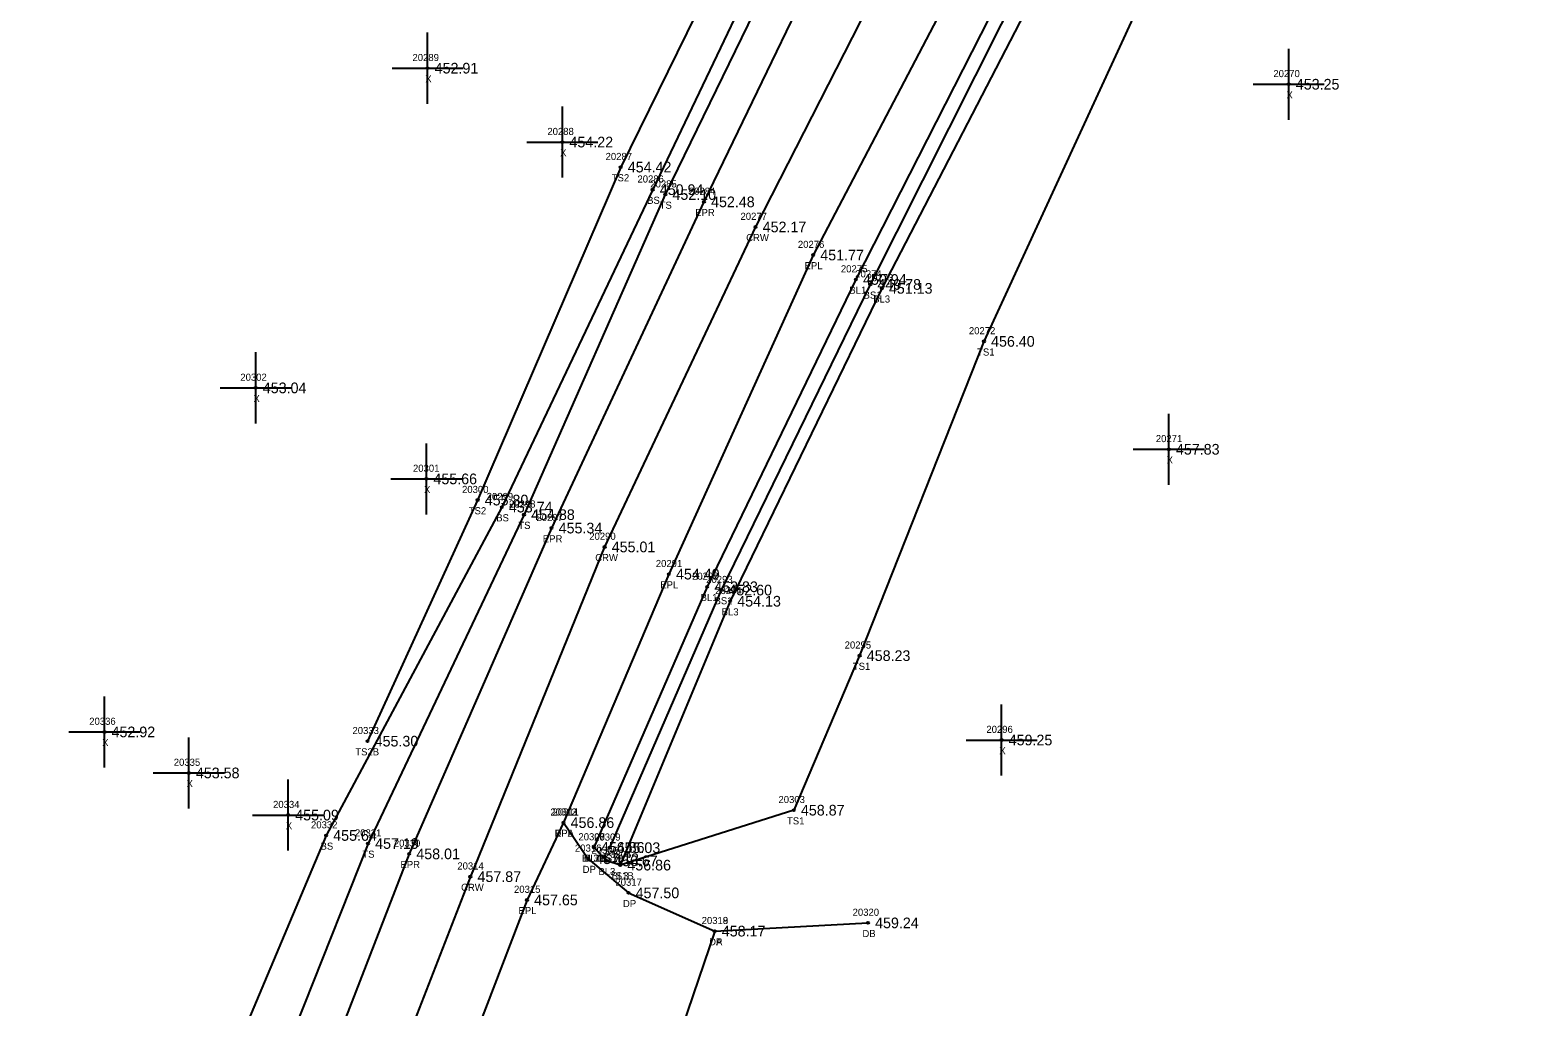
# Model space of a CAD drawing. Extents: x 1763022 to 1764007, y 824123 to 825394.
# Drawn here: x 1763289.5 to 1763501.5, y 824553.5 to 824690.9 of the extents above; entities that cross this region are included whole.
import ezdxf

# ---------------------------------------------------------------- set-up
doc = ezdxf.new("R2010")
doc.units = 0
for name, color, linetype in [('RD_DTM_BkLn1', 7, 'Continuous'), ('RD_DTM_BkLn2', 7, 'Continuous'), ('RD_DTM_BkLn_txCode', 7, 'Continuous'), ('RD_EX_Driveway', 7, 'Continuous'), ('RD_EX_Driveway_txCode', 7, 'Continuous'), ('RD_EX_Misc', 7, 'Continuous'), ('RD_EX_Misc_txCode', 7, 'Continuous'), ('RD_EX_Road', 7, 'Continuous'), ('RD_EX_Road_txCode', 7, 'Continuous'), ('RD_EX_TX_Driveway_ELEV', 7, 'Continuous'), ('RD_EX_TX_Misc_ELEV', 7, 'Continuous'), ('RD_EX_TX_Road_ELEV', 7, 'Continuous'), ('RD_HC_Survey_ELEV', 7, 'Continuous'), ('RD_HC_Survey_txCode', 7, 'Continuous'), ('RD_SMD_Locator', 7, 'Continuous')]:
    doc.layers.add(name, color=color, linetype=linetype)

msp = doc.modelspace()

# ---------------------------------------------------------------- linework, layer by layer
at = {"layer": 'RD_DTM_BkLn1'}
for points in [[(1763465.6, 824795.18), (1763438.99, 824751.97), (1763414.16, 824707.73), (1763391.5, 824663.21), (1763370.27, 824618.19), (1763351.39, 824571.8), (1763333.36, 824525.39), (1763297, 824431.97), (1763261.49, 824337.79), (1763225.86, 824243.32), (1763189.96, 824148.95)], [(1763449.11, 824737.2), (1763428.21, 824700.24), (1763405.61, 824655.82), (1763384.69, 824612.58), (1763368.75, 824575.91)], [(1763452.61, 824734.75), (1763432, 824698.5), (1763409.25, 824654.57), (1763387.93, 824610.55), (1763372.47, 824573.42), (1763370.6, 824574.02), (1763368.75, 824575.91)]]:
    msp.add_lwpolyline(points, dxfattribs=at)
at = {"layer": 'RD_DTM_BkLn2'}
for points in [[(1763437.34, 824834), (1763430.66, 824820.06), (1763415.77, 824811.96), (1763415.35, 824798.51), (1763416.46, 824790.14), (1763418.19, 824781.43), (1763421.71, 824775.16), (1763417.19, 824763.87), (1763415.91, 824751.32), (1763399.06, 824714.58), (1763377.03, 824668.46), (1763355.81, 824623.79), (1763331.1, 824577.59), (1763312.25, 824532.84), (1763306.13, 824522.15), (1763306.75, 824510.59), (1763289.07, 824468.95), (1763279.57, 824438.1), (1763246.06, 824343.25), (1763209.87, 824247.25), (1763175.28, 824154.06)], [(1763453.01, 824802.49), (1763449.47, 824806.22), (1763441.02, 824809.92), (1763431.56, 824802.85), (1763425.71, 824792.63), (1763430.16, 824781.29), (1763430.95, 824776.81), (1763424.71, 824760.36), (1763418.93, 824749.28), (1763401.15, 824713.73), (1763378.81, 824667.77), (1763358.94, 824622.73), (1763337, 824576.46), (1763318.92, 824530.87), (1763314.75, 824518.63), (1763292.84, 824467.34), (1763282.85, 824437.24), (1763248.29, 824342.54), (1763211.77, 824246.85), (1763177.66, 824153.22)], [(1763510.31, 824776.41), (1763487.73, 824739.69), (1763467.72, 824746.4), (1763457.88, 824742.49), (1763448.32, 824732.5), (1763429.76, 824699.16), (1763407.64, 824655.12), (1763386.68, 824612.12), (1763370.96, 824575.87)], [(1763412.55, 824767.8), (1763413.66, 824764.06), (1763414.47, 824751.79), (1763395.05, 824717.48), (1763372.53, 824671.63), (1763352.41, 824624.78), (1763336.93, 824590.86)], [(1763459.29, 824736.58), (1763444.88, 824693.27), (1763423.62, 824647.11), (1763406.14, 824602.89), (1763396.88, 824581.15), (1763372.47, 824573.42)]]:
    msp.add_lwpolyline(points, dxfattribs=at)
at = {"layer": 'RD_EX_Driveway'}
msp.add_line((1763385.75, 824564.13), (1763407.31, 824565.29), dxfattribs=at)
msp.add_lwpolyline([(1763364.49, 824579.4), (1763367.96, 824574.32), (1763373.63, 824569.51), (1763385.75, 824564.13), (1763378.09, 824541.5), (1763366.26, 824546.2), (1763360.49, 824545.69), (1763347.68, 824537.95)], dxfattribs=at)
at = {"layer": 'RD_EX_Misc'}
for p, q in [((1763345.37, 824680.55), (1763345.37, 824690.55)), ((1763466.48, 824678.29), (1763466.48, 824688.29)), ((1763340.37, 824685.55), (1763350.37, 824685.55)), ((1763461.48, 824683.29), (1763471.48, 824683.29)), ((1763364.33, 824670.15), (1763364.33, 824680.15)), ((1763359.33, 824675.15), (1763369.33, 824675.15)), ((1763321.2, 824635.57), (1763321.2, 824645.57)), ((1763316.2, 824640.57), (1763326.2, 824640.57)), ((1763449.62, 824626.93), (1763449.62, 824636.93)), ((1763345.2, 824622.76), (1763345.2, 824632.76)), ((1763444.62, 824631.93), (1763454.62, 824631.93)), ((1763340.2, 824627.76), (1763350.2, 824627.76)), ((1763299.93, 824587.16), (1763299.93, 824597.16)), ((1763426.1, 824586.02), (1763426.1, 824596.02)), ((1763294.93, 824592.16), (1763304.93, 824592.16)), ((1763311.79, 824581.39), (1763311.79, 824591.39)), ((1763421.1, 824591.02), (1763431.1, 824591.02)), ((1763306.79, 824586.39), (1763316.79, 824586.39)), ((1763325.76, 824575.46), (1763325.76, 824585.46)), ((1763320.76, 824580.46), (1763330.76, 824580.46))]:
    msp.add_line(p, q, dxfattribs=at)
at = {"layer": 'RD_EX_Road'}
for points in [[(1763458.16, 824800.38), (1763431, 824756.75), (1763406.01, 824711.9), (1763384.24, 824666.74), (1763362.81, 824620.84), (1763342.79, 824575), (1763324.89, 824528.78), (1763288.3, 824435.22), (1763252.09, 824341.05), (1763216.31, 824245.88), (1763180.37, 824152.33)], [(1763474.08, 824789.56), (1763447.08, 824747.55), (1763422.65, 824703.33), (1763399.6, 824659.26), (1763379.31, 824614.36), (1763364.49, 824579.4), (1763364.49, 824579.4), (1763359.36, 824568.52), (1763347.68, 824537.95), (1763341.79, 824522.26), (1763305.94, 824428.62), (1763270.17, 824334.76), (1763235.03, 824239.84), (1763198.43, 824144.73)]]:
    msp.add_lwpolyline(points, dxfattribs=at)
at = {"layer": 'RD_SMD_Locator'}
for centre in [(1763345.37, 824685.55), (1763466.48, 824683.29), (1763364.33, 824675.15), (1763372.53, 824671.63), (1763377.03, 824668.46), (1763378.81, 824667.77), (1763384.24, 824666.74), (1763391.5, 824663.21), (1763399.6, 824659.26), (1763405.61, 824655.82), (1763407.64, 824655.12), (1763409.25, 824654.57), (1763423.62, 824647.11), (1763321.2, 824640.57), (1763449.62, 824631.93), (1763345.2, 824627.76), (1763352.41, 824624.78), (1763355.81, 824623.79), (1763358.94, 824622.73), (1763362.81, 824620.84), (1763370.27, 824618.19), (1763379.31, 824614.36), (1763384.69, 824612.58), (1763386.68, 824612.12), (1763387.93, 824610.55), (1763406.14, 824602.89), (1763299.93, 824592.16), (1763336.93, 824590.86), (1763426.1, 824591.02), (1763311.79, 824586.39), (1763325.76, 824580.46), (1763396.88, 824581.15), (1763364.49, 824579.4), (1763364.49, 824579.4), (1763364.49, 824579.4), (1763331.1, 824577.59), (1763337, 824576.46), (1763368.75, 824575.91), (1763368.75, 824575.91), (1763370.96, 824575.87), (1763342.79, 824575), (1763367.96, 824574.32), (1763370.6, 824574.02), (1763351.39, 824571.8), (1763372.47, 824573.42), (1763372.47, 824573.42), (1763373.63, 824569.51), (1763359.36, 824568.52), (1763407.31, 824565.29), (1763385.75, 824564.13), (1763385.75, 824564.13)]:
    msp.add_circle(centre, 0.15, dxfattribs=at)

# ---------------------------------------------------------------- texts
at = {"layer": 'RD_DTM_BkLn_txCode'}
for s, p in [('20287', (1763370.41, 824672.63)), ('TS2', (1763371.28, 824669.63)), ('20286', (1763374.89, 824669.46)), ('20285', (1763376.69, 824668.77)), ('BS', (1763376.25, 824666.46)), ('TS', (1763378.01, 824665.77)), ('20275', (1763403.5, 824656.82)), ('20274', (1763405.52, 824656.12)), ('20273', (1763407.13, 824655.57)), ('BL1', (1763404.69, 824653.82)), ('BS1', (1763406.69, 824653.12)), ('BL3', (1763408.04, 824652.57)), ('20272', (1763421.5, 824648.11)), ('TS1', (1763422.66, 824645.11)), ('20300', (1763350.22, 824625.78)), ('20299', (1763353.69, 824624.79)), ('TS2', (1763351.17, 824622.78)), ('BS', (1763355.03, 824621.79)), ('20298', (1763356.82, 824623.73)), ('TS', (1763358.14, 824620.73)), ('20292', (1763382.57, 824613.58)), ('20293', (1763384.56, 824613.12)), ('20294', (1763385.82, 824611.55)), ('BL1', (1763383.77, 824610.58)), ('BS1', (1763385.73, 824610.12)), ('BL3', (1763386.73, 824608.55)), ('20295', (1763404.03, 824603.89)), ('TS1', (1763405.18, 824600.89)), ('20333', (1763334.81, 824591.86)), ('TS2B', (1763335.21, 824588.86)), ('20303', (1763394.72, 824582.15)), ('20332', (1763328.98, 824578.59)), ('20331', (1763335.16, 824577.46)), ('TS1', (1763395.92, 824579.15)), ('BS', (1763330.32, 824575.59)), ('20307', (1763366.59, 824576.91)), ('20308', (1763366.59, 824576.91)), ('20306', (1763368.42, 824575.02)), ('20309', (1763368.8, 824576.87)), ('TS', (1763336.2, 824574.46)), ('BL3B', (1763367.07, 824573.91)), ('BL1B', (1763367.36, 824573.91)), ('BS1B', (1763369.54, 824573.87)), ('20304', (1763370.31, 824574.42)), ('20305', (1763370.31, 824574.42)), ('BL3', (1763369.4, 824572.02)), ('TS1B', (1763371.03, 824571.42)), ('BL3', (1763371.26, 824571.42))]:
    msp.add_text(s, height=1, dxfattribs=at).set_placement(p)
at = {"layer": 'RD_EX_Driveway_txCode'}
for s, p in [('20313', (1763362.65, 824580.4)), ('DPA', (1763363.22, 824577.4)), ('20316', (1763366.1, 824575.32)), ('DP', (1763367.18, 824572.32)), ('20317', (1763371.79, 824570.51)), ('DP', (1763372.85, 824567.51)), ('20318', (1763383.92, 824565.13)), ('20319', (1763383.92, 824565.13)), ('20320', (1763405.15, 824566.29)), ('DB', (1763406.53, 824563.29)), ('DA', (1763384.96, 824562.13)), ('DP', (1763384.97, 824562.13))]:
    msp.add_text(s, height=1, dxfattribs=at).set_placement(p)
at = {"layer": 'RD_EX_Misc_txCode'}
for s, p in [('20289', (1763343.25, 824686.55)), ('X', (1763345.05, 824683.55)), ('20270', (1763464.32, 824684.29)), ('X', (1763466.16, 824681.29)), ('20288', (1763362.22, 824676.15)), ('X', (1763364.02, 824673.15)), ('20302', (1763319.04, 824641.57)), ('X', (1763320.89, 824638.57)), ('20271', (1763447.79, 824632.93)), ('20301', (1763343.32, 824628.76)), ('X', (1763449.31, 824629.93)), ('X', (1763344.88, 824625.76)), ('20336', (1763297.79, 824593.16)), ('20296', (1763423.96, 824592.02)), ('X', (1763299.61, 824590.16)), ('X', (1763425.78, 824589.02)), ('20335', (1763309.68, 824587.39)), ('X', (1763311.48, 824584.39)), ('20334', (1763323.64, 824581.46)), ('X', (1763325.44, 824578.46))]:
    msp.add_text(s, height=1, dxfattribs=at).set_placement(p)
at = {"layer": 'RD_EX_Road_txCode'}
for s, p in [('20284', (1763382.12, 824667.74)), ('EPR', (1763383.01, 824664.74)), ('20276', (1763397.45, 824660.26)), ('EPL', (1763398.39, 824657.26)), ('20297', (1763360.69, 824621.84)), ('EPR', (1763361.58, 824618.84)), ('20291', (1763377.47, 824615.36)), ('EPL', (1763378.1, 824612.36)), ('20312', (1763362.65, 824580.4)), ('20311', (1763362.94, 824580.4)), ('EPL', (1763363.28, 824577.4)), ('EPL', (1763363.28, 824577.4)), ('20330', (1763340.63, 824576)), ('EPR', (1763341.56, 824573)), ('20315', (1763357.53, 824569.52)), ('EPL', (1763358.16, 824566.52))]:
    msp.add_text(s, height=1, dxfattribs=at).set_placement(p)
at = {"layer": 'RD_EX_TX_Driveway_ELEV'}
for s, p in [('456.86', (1763365.49, 824578.65)), ('457.12', (1763368.96, 824573.57)), ('457.50', (1763374.63, 824568.76)), ('459.24', (1763408.31, 824564.54)), ('458.17', (1763386.75, 824563.38)), ('458.17', (1763386.75, 824563.38))]:
    msp.add_text(s, height=1.5, dxfattribs=at).set_placement(p)
at = {"layer": 'RD_EX_TX_Misc_ELEV'}
for s, p in [('452.91', (1763346.37, 824684.8)), ('453.25', (1763467.48, 824682.54)), ('454.22', (1763365.33, 824674.4)), ('454.42', (1763373.53, 824670.88)), ('450.94', (1763378.03, 824667.71)), ('452.10', (1763379.81, 824667.02)), ('450.94', (1763406.61, 824655.07)), ('449.78', (1763408.64, 824654.37)), ('451.13', (1763410.25, 824653.82)), ('456.40', (1763424.62, 824646.36)), ('453.04', (1763322.2, 824639.82)), ('457.83', (1763450.62, 824631.18)), ('455.66', (1763346.2, 824627.01)), ('455.80', (1763353.41, 824624.03)), ('453.74', (1763356.81, 824623.04)), ('454.88', (1763359.94, 824621.98)), ('453.83', (1763385.69, 824611.83)), ('452.60', (1763387.68, 824611.37)), ('454.13', (1763388.93, 824609.8)), ('458.23', (1763407.14, 824602.14)), ('452.92', (1763300.93, 824591.41)), ('455.30', (1763337.93, 824590.11)), ('459.25', (1763427.1, 824590.27)), ('453.58', (1763312.79, 824585.64)), ('455.09', (1763326.76, 824579.71)), ('458.87', (1763397.88, 824580.4)), ('455.64', (1763332.1, 824576.84)), ('457.19', (1763338, 824575.71)), ('456.86', (1763369.75, 824575.16)), ('456.86', (1763369.75, 824575.16)), ('455.03', (1763371.96, 824575.12)), ('456.67', (1763371.6, 824573.27)), ('456.86', (1763373.47, 824572.67)), ('456.86', (1763373.47, 824572.67))]:
    msp.add_text(s, height=1.5, dxfattribs=at).set_placement(p)
at = {"layer": 'RD_EX_TX_Road_ELEV'}
for s, p in [('452.48', (1763385.24, 824665.99)), ('451.77', (1763400.6, 824658.51)), ('455.34', (1763363.81, 824620.09)), ('454.49', (1763380.31, 824613.61)), ('456.86', (1763365.49, 824578.65)), ('456.86', (1763365.49, 824578.65)), ('458.01', (1763343.79, 824574.25)), ('457.65', (1763360.36, 824567.77))]:
    msp.add_text(s, height=1.5, dxfattribs=at).set_placement(p)
at = {"layer": 'RD_HC_Survey_ELEV'}
for s, p in [('452.17', (1763392.5, 824662.46)), ('455.01', (1763371.27, 824617.44)), ('457.87', (1763352.39, 824571.05))]:
    msp.add_text(s, height=1.5, dxfattribs=at).set_placement(p)
at = {"layer": 'RD_HC_Survey_txCode'}
for s, p in [('20277', (1763389.38, 824664.21)), ('CRW', (1763390.18, 824661.21)), ('20290', (1763368.11, 824619.19)), ('CRW', (1763368.95, 824616.19)), ('20314', (1763349.56, 824572.8)), ('CRW', (1763350.08, 824569.8))]:
    msp.add_text(s, height=1, dxfattribs=at).set_placement(p)

doc.saveas('drawing.dxf')
